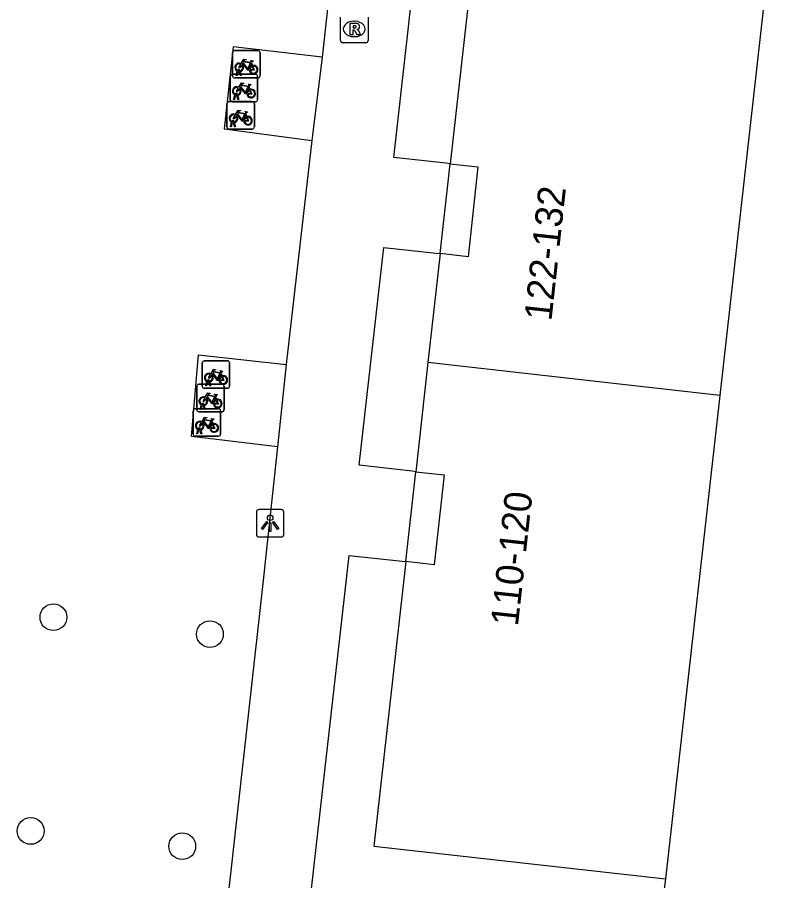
# Model space of a CAD drawing. Extents: x 161928 to 163055, y 386475 to 387428.
# Drawn here: x 162252.98 to 162280.57, y 386677.61 to 386709.1 of the extents above; entities that cross this region are included whole.
import ezdxf

# ---------------------------------------------------------------- set-up
doc = ezdxf.new("R2010")
doc.units = 0
for name, color, linetype in [('IMGEO_Boom', 7, 'Continuous'), ('IMGEO_Fietsenrek', 7, 'Continuous'), ('IMGEO_Grasland_overig', 7, 'Continuous'), ('IMGEO_Lichtpunt', 7, 'Continuous'), ('IMGEO_Pand', 7, 'Continuous'), ('IMGEO_Pand_nummerreeks', 7, 'Continuous'), ('IMGEO_Rioolput', 7, 'Continuous'), ('IMGEO_Voetpad_open', 7, 'Continuous')]:
    doc.layers.add(name, color=color, linetype=linetype)

msp = doc.modelspace()

# ---------------------------------------------------------------- linework, layer by layer
at = {"layer": 'IMGEO_Boom'}
for centre in [(162254.296, 386687.22), (162260.002, 386686.602), (162253.466, 386679.427), (162258.994, 386678.87)]:
    msp.add_circle(centre, 0.489, dxfattribs=at)
at = {"layer": 'IMGEO_Fietsenrek'}
for p, q in [((162260.905, 386707.882), (162261.746, 386707.882)), ((162261.746, 386707.882), (162260.905, 386707.882)), ((162260.83, 386706.957), (162260.83, 386707.798)), ((162260.83, 386707.798), (162260.83, 386706.957)), ((162261.83, 386707.807), (162261.83, 386706.966)), ((162261.83, 386706.966), (162261.83, 386707.807)), ((162261.517, 386707.431), (162261.553, 386707.336)), ((162260.741, 386706.091), (162260.741, 386706.932)), ((162260.741, 386706.932), (162260.741, 386706.091)), ((162260.816, 386707.016), (162261.657, 386707.016)), ((162261.657, 386707.016), (162260.816, 386707.016)), ((162260.957, 386706.966), (162260.996, 386707.126)), ((162260.991, 386706.966), (162260.957, 386706.966)), ((162261.026, 386707.114), (162260.991, 386706.966)), ((162261.068, 386707.138), (162261.067, 386707.142)), ((162261.109, 386706.966), (162261.075, 386707.108)), ((162261.099, 386707.149), (162261.1, 386707.142)), ((162261.107, 386707.112), (162261.142, 386706.966)), ((162261.142, 386706.966), (162261.109, 386706.966)), ((162261.741, 386706.941), (162261.741, 386706.1)), ((162261.741, 386706.1), (162261.741, 386706.941)), ((162261.755, 386706.882), (162260.914, 386706.882)), ((162260.914, 386706.882), (162261.755, 386706.882)), ((162260.979, 386706.272), (162260.978, 386706.276)), ((162261.01, 386706.283), (162261.011, 386706.276)), ((162261.428, 386706.565), (162261.464, 386706.47)), ((162260.698, 386706.021), (162261.539, 386706.021)), ((162261.539, 386706.021), (162260.698, 386706.021)), ((162261.666, 386706.016), (162260.825, 386706.016)), ((162260.825, 386706.016), (162261.666, 386706.016)), ((162260.868, 386706.1), (162260.907, 386706.26)), ((162260.902, 386706.1), (162260.868, 386706.1)), ((162260.937, 386706.248), (162260.902, 386706.1)), ((162261.02, 386706.1), (162260.986, 386706.242)), ((162261.018, 386706.246), (162261.053, 386706.1)), ((162261.053, 386706.1), (162261.02, 386706.1)), ((162260.623, 386705.096), (162260.623, 386705.937)), ((162260.623, 386705.937), (162260.623, 386705.096)), ((162261.623, 386705.946), (162261.623, 386705.105)), ((162261.623, 386705.105), (162261.623, 386705.946)), ((162261.31, 386705.57), (162261.346, 386705.475)), ((162261.548, 386705.021), (162260.707, 386705.021)), ((162260.707, 386705.021), (162261.548, 386705.021)), ((162260.75, 386705.105), (162260.789, 386705.265)), ((162260.784, 386705.105), (162260.75, 386705.105)), ((162260.819, 386705.253), (162260.784, 386705.105)), ((162260.861, 386705.277), (162260.86, 386705.281)), ((162260.902, 386705.105), (162260.868, 386705.247)), ((162260.892, 386705.288), (162260.893, 386705.281)), ((162260.9, 386705.251), (162260.935, 386705.105)), ((162260.935, 386705.105), (162260.902, 386705.105)), ((162259.798, 386696.569), (162260.639, 386696.569)), ((162260.639, 386696.569), (162259.798, 386696.569)), ((162259.723, 386695.644), (162259.723, 386696.485)), ((162259.723, 386696.485), (162259.723, 386695.644)), ((162260.723, 386696.494), (162260.723, 386695.653)), ((162260.723, 386695.653), (162260.723, 386696.494)), ((162260.41, 386696.118), (162260.446, 386696.023)), ((162259.522, 386694.787), (162259.522, 386695.628)), ((162259.522, 386695.628), (162259.522, 386694.787)), ((162259.597, 386695.712), (162260.438, 386695.712)), ((162260.438, 386695.712), (162259.597, 386695.712)), ((162260.648, 386695.569), (162259.807, 386695.569)), ((162259.807, 386695.569), (162260.648, 386695.569)), ((162259.85, 386695.653), (162259.889, 386695.813)), ((162259.884, 386695.653), (162259.85, 386695.653)), ((162259.919, 386695.801), (162259.884, 386695.653)), ((162259.961, 386695.825), (162259.96, 386695.829)), ((162260.002, 386695.653), (162259.968, 386695.795)), ((162259.992, 386695.836), (162259.993, 386695.829)), ((162260, 386695.799), (162260.035, 386695.653)), ((162260.035, 386695.653), (162260.002, 386695.653)), ((162260.522, 386695.637), (162260.522, 386694.796)), ((162260.522, 386694.796), (162260.522, 386695.637)), ((162260.209, 386695.261), (162260.245, 386695.166)), ((162259.649, 386694.796), (162259.688, 386694.956)), ((162259.718, 386694.944), (162259.683, 386694.796)), ((162259.76, 386694.968), (162259.759, 386694.972)), ((162259.801, 386694.796), (162259.767, 386694.938)), ((162259.791, 386694.979), (162259.792, 386694.972)), ((162259.799, 386694.942), (162259.834, 386694.796)), ((162259.393, 386693.895), (162259.393, 386694.736)), ((162259.393, 386694.736), (162259.393, 386693.895)), ((162259.468, 386694.82), (162260.309, 386694.82)), ((162260.309, 386694.82), (162259.468, 386694.82)), ((162260.447, 386694.712), (162259.606, 386694.712)), ((162259.606, 386694.712), (162260.447, 386694.712)), ((162259.683, 386694.796), (162259.649, 386694.796)), ((162259.834, 386694.796), (162259.801, 386694.796)), ((162260.393, 386694.745), (162260.393, 386693.904)), ((162260.393, 386693.904), (162260.393, 386694.745)), ((162260.08, 386694.369), (162260.116, 386694.274)), ((162259.52, 386693.904), (162259.559, 386694.064)), ((162259.589, 386694.052), (162259.554, 386693.904)), ((162259.631, 386694.076), (162259.63, 386694.08)), ((162259.672, 386693.904), (162259.638, 386694.046)), ((162259.662, 386694.087), (162259.663, 386694.08)), ((162259.67, 386694.05), (162259.705, 386693.904)), ((162260.318, 386693.82), (162259.477, 386693.82)), ((162259.477, 386693.82), (162260.318, 386693.82)), ((162259.554, 386693.904), (162259.52, 386693.904)), ((162259.705, 386693.904), (162259.672, 386693.904))]:
    msp.add_line(p, q, dxfattribs=at)
for points in [[(162261.143, 386707.408), (162261.238, 386707.572), (162261.324, 386707.558), (162261.326, 386707.549), (162261.27, 386707.538), (162261.243, 386707.493), (162261.499, 386707.452)], [(162261.164, 386707.356), (162261.112, 386707.266), (162261.072, 386707.241), (162261.073, 386707.288), (162261.128, 386707.382)], [(162261.439, 386707.164), (162261.389, 386707.164), (162261.198, 386707.415), (162261.179, 386707.383)], [(162261.486, 386707.427), (162261.229, 386707.468), (162261.212, 386707.439), (162261.379, 386707.219), (162261.486, 386707.427)], [(162261.534, 386707.329), (162261.504, 386707.406), (162261.395, 386707.188), (162261.438, 386707.188)], [(162261.468, 386707.188), (162261.588, 386707.187), (162261.544, 386707.301)], [(162261.564, 386707.308), (162261.619, 386707.163), (162261.469, 386707.163)], [(162261.499, 386707.452), (162261.524, 386707.501), (162261.518, 386707.505), (162261.495, 386707.509), (162261.483, 386707.516), (162261.482, 386707.519), (162261.484, 386707.524), (162261.579, 386707.509), (162261.581, 386707.499), (162261.571, 386707.486), (162261.559, 386707.48), (162261.545, 386707.486), (162261.517, 386707.431)], [(162261.054, 386706.542), (162261.149, 386706.706), (162261.235, 386706.692), (162261.237, 386706.683), (162261.181, 386706.672), (162261.154, 386706.627), (162261.41, 386706.586)], [(162261.397, 386706.561), (162261.14, 386706.602), (162261.123, 386706.573), (162261.29, 386706.353), (162261.397, 386706.561)], [(162261.41, 386706.586), (162261.435, 386706.635), (162261.429, 386706.639), (162261.406, 386706.643), (162261.394, 386706.65), (162261.393, 386706.653), (162261.395, 386706.658), (162261.49, 386706.643), (162261.492, 386706.633), (162261.482, 386706.62), (162261.47, 386706.614), (162261.456, 386706.62), (162261.428, 386706.565)], [(162261.075, 386706.49), (162261.023, 386706.4), (162260.983, 386706.375), (162260.984, 386706.422), (162261.039, 386706.516)], [(162261.35, 386706.298), (162261.3, 386706.298), (162261.109, 386706.549), (162261.09, 386706.517)], [(162261.445, 386706.463), (162261.415, 386706.54), (162261.306, 386706.322), (162261.349, 386706.322)], [(162261.379, 386706.322), (162261.499, 386706.321), (162261.455, 386706.435)], [(162261.475, 386706.442), (162261.53, 386706.297), (162261.38, 386706.297)], [(162260.936, 386705.547), (162261.031, 386705.711), (162261.117, 386705.697), (162261.119, 386705.688), (162261.063, 386705.677), (162261.036, 386705.632), (162261.292, 386705.591)], [(162261.292, 386705.591), (162261.317, 386705.64), (162261.311, 386705.644), (162261.288, 386705.648), (162261.276, 386705.655), (162261.275, 386705.658), (162261.277, 386705.663), (162261.372, 386705.648), (162261.374, 386705.638), (162261.364, 386705.625), (162261.352, 386705.619), (162261.338, 386705.625), (162261.31, 386705.57)], [(162260.957, 386705.495), (162260.905, 386705.405), (162260.865, 386705.38), (162260.866, 386705.427), (162260.921, 386705.521)], [(162261.232, 386705.303), (162261.182, 386705.303), (162260.991, 386705.554), (162260.972, 386705.522)], [(162261.279, 386705.566), (162261.022, 386705.607), (162261.005, 386705.578), (162261.172, 386705.358), (162261.279, 386705.566)], [(162261.327, 386705.468), (162261.297, 386705.545), (162261.188, 386705.327), (162261.231, 386705.327)], [(162261.261, 386705.327), (162261.381, 386705.326), (162261.337, 386705.44)], [(162261.357, 386705.447), (162261.412, 386705.302), (162261.262, 386705.302)], [(162260.036, 386696.095), (162260.131, 386696.259), (162260.217, 386696.245), (162260.219, 386696.236), (162260.163, 386696.225), (162260.136, 386696.18), (162260.392, 386696.139)], [(162260.392, 386696.139), (162260.417, 386696.188), (162260.411, 386696.192), (162260.388, 386696.196), (162260.376, 386696.203), (162260.375, 386696.206), (162260.377, 386696.211), (162260.472, 386696.196), (162260.474, 386696.186), (162260.464, 386696.173), (162260.452, 386696.167), (162260.438, 386696.173), (162260.41, 386696.118)], [(162260.057, 386696.043), (162260.005, 386695.953), (162259.965, 386695.928), (162259.966, 386695.975), (162260.021, 386696.069)], [(162260.332, 386695.851), (162260.282, 386695.851), (162260.091, 386696.102), (162260.072, 386696.07)], [(162260.379, 386696.114), (162260.122, 386696.155), (162260.105, 386696.126), (162260.272, 386695.906), (162260.379, 386696.114)], [(162260.427, 386696.016), (162260.397, 386696.093), (162260.288, 386695.875), (162260.331, 386695.875)], [(162260.361, 386695.875), (162260.481, 386695.874), (162260.437, 386695.988)], [(162260.457, 386695.995), (162260.512, 386695.85), (162260.362, 386695.85)], [(162259.835, 386695.238), (162259.93, 386695.402), (162260.016, 386695.388), (162260.018, 386695.379), (162259.962, 386695.368), (162259.935, 386695.323), (162260.191, 386695.282)], [(162260.178, 386695.257), (162259.921, 386695.298), (162259.904, 386695.269), (162260.071, 386695.049), (162260.178, 386695.257)], [(162260.191, 386695.282), (162260.216, 386695.331), (162260.21, 386695.335), (162260.187, 386695.339), (162260.175, 386695.346), (162260.174, 386695.349), (162260.176, 386695.354), (162260.271, 386695.339), (162260.273, 386695.329), (162260.263, 386695.316), (162260.251, 386695.31), (162260.237, 386695.316), (162260.209, 386695.261)], [(162259.856, 386695.186), (162259.804, 386695.096), (162259.764, 386695.071), (162259.765, 386695.118), (162259.82, 386695.212)], [(162260.131, 386694.994), (162260.081, 386694.994), (162259.89, 386695.245), (162259.871, 386695.213)], [(162260.226, 386695.159), (162260.196, 386695.236), (162260.087, 386695.018), (162260.13, 386695.018)], [(162260.16, 386695.018), (162260.28, 386695.017), (162260.236, 386695.131)], [(162260.256, 386695.138), (162260.311, 386694.993), (162260.161, 386694.993)], [(162259.727, 386694.294), (162259.675, 386694.204), (162259.635, 386694.179), (162259.636, 386694.226), (162259.691, 386694.32)], [(162259.706, 386694.346), (162259.801, 386694.51), (162259.887, 386694.496), (162259.889, 386694.487), (162259.833, 386694.476), (162259.806, 386694.431), (162260.062, 386694.39)], [(162260.002, 386694.102), (162259.952, 386694.102), (162259.761, 386694.353), (162259.742, 386694.321)], [(162260.049, 386694.365), (162259.792, 386694.406), (162259.775, 386694.377), (162259.942, 386694.157), (162260.049, 386694.365)], [(162260.097, 386694.267), (162260.067, 386694.344), (162259.958, 386694.126), (162260.001, 386694.126)], [(162260.062, 386694.39), (162260.087, 386694.439), (162260.081, 386694.443), (162260.058, 386694.447), (162260.046, 386694.454), (162260.045, 386694.457), (162260.047, 386694.462), (162260.142, 386694.447), (162260.144, 386694.437), (162260.134, 386694.424), (162260.122, 386694.418), (162260.108, 386694.424), (162260.08, 386694.369)], [(162260.031, 386694.126), (162260.151, 386694.125), (162260.107, 386694.239)], [(162260.127, 386694.246), (162260.182, 386694.101), (162260.032, 386694.101)]]:
    msp.add_lwpolyline(points, dxfattribs=at)
for centre, radius, start, end in [((162260.908, 386707.804), 0.0779, 92.4484, 184.2845), ((162260.908, 386707.804), 0.0779, 92.4484, 184.2845), ((162261.752, 386707.804), 0.0779, 2.4484, 94.2845), ((162261.752, 386707.804), 0.0779, 2.4484, 94.2845), ((162261.07, 386707.267), 0.159, 62.6766, 242.1369), ((162261.07, 386707.267), 0.129, 63.3192, 238.903), ((162261.07, 386707.267), 0.129, 283.6043, 43.4302), ((162261.07, 386707.267), 0.159, 283.5766, 46.6042), ((162261.597, 386707.183), 0.159, 113.3408, 178.3217), ((162261.597, 386707.183), 0.159, 187.0065, 105.7708), ((162261.597, 386707.183), 0.129, 113.923, 177.9556), ((162261.597, 386707.183), 0.129, 188.6715, 104.5883), ((162260.819, 386706.938), 0.0779, 92.4484, 184.2845), ((162260.819, 386706.938), 0.0779, 92.4484, 184.2845), ((162260.908, 386706.96), 0.0779, 182.4484, 274.2845), ((162260.908, 386706.96), 0.0779, 182.4484, 274.2845), ((162261.05, 386707.138), 0.0499, 12.8025, 158.6934), ((162261.07, 386707.267), 0.159, 253.9967, 271.7867), ((162261.05, 386707.138), 0.0174, 12.8025, 163.4502), ((162261.07, 386707.267), 0.129, 253.415, 269.0204), ((162261.663, 386706.938), 0.0779, 2.4484, 94.2845), ((162261.663, 386706.938), 0.0779, 2.4484, 94.2845), ((162261.752, 386706.96), 0.0779, 272.4484, 4.2845), ((162261.752, 386706.96), 0.0779, 272.4484, 4.2845), ((162260.981, 386706.401), 0.159, 62.6766, 242.1369), ((162260.981, 386706.401), 0.129, 63.3192, 238.903), ((162260.961, 386706.272), 0.0499, 12.8025, 158.6934), ((162260.961, 386706.272), 0.0174, 12.8025, 163.4502), ((162260.981, 386706.401), 0.129, 253.415, 269.0204), ((162260.981, 386706.401), 0.129, 283.6043, 43.4302), ((162260.981, 386706.401), 0.159, 283.5766, 46.6042), ((162261.508, 386706.317), 0.159, 113.3408, 178.3217), ((162261.508, 386706.317), 0.159, 187.0065, 105.7708), ((162261.508, 386706.317), 0.129, 113.923, 177.9556), ((162261.508, 386706.317), 0.129, 188.6715, 104.5883), ((162260.701, 386705.943), 0.0779, 92.4484, 184.2845), ((162260.701, 386705.943), 0.0779, 92.4484, 184.2845), ((162260.819, 386706.094), 0.0779, 182.4484, 274.2845), ((162260.819, 386706.094), 0.0779, 182.4484, 274.2845), ((162260.981, 386706.401), 0.159, 253.9967, 271.7867), ((162261.545, 386705.943), 0.0779, 2.4484, 94.2845), ((162261.545, 386705.943), 0.0779, 2.4484, 94.2845), ((162261.663, 386706.094), 0.0779, 272.4484, 4.2845), ((162261.663, 386706.094), 0.0779, 272.4484, 4.2845), ((162260.863, 386705.406), 0.159, 62.6766, 242.1369), ((162260.863, 386705.406), 0.129, 63.3192, 238.903), ((162260.863, 386705.406), 0.129, 283.6043, 43.4302), ((162260.863, 386705.406), 0.159, 283.5766, 46.6042), ((162261.39, 386705.322), 0.159, 113.3408, 178.3217), ((162261.39, 386705.322), 0.159, 187.0065, 105.7708), ((162261.39, 386705.322), 0.129, 113.923, 177.9556), ((162261.39, 386705.322), 0.129, 188.6715, 104.5883), ((162260.701, 386705.099), 0.0779, 182.4484, 274.2845), ((162260.701, 386705.099), 0.0779, 182.4484, 274.2845), ((162260.843, 386705.277), 0.0499, 12.8025, 158.6934), ((162260.863, 386705.406), 0.159, 253.9967, 271.7867), ((162260.843, 386705.277), 0.0174, 12.8025, 163.4502), ((162260.863, 386705.406), 0.129, 253.415, 269.0204), ((162261.545, 386705.099), 0.0779, 272.4484, 4.2845), ((162261.545, 386705.099), 0.0779, 272.4484, 4.2845), ((162259.801, 386696.491), 0.0779, 92.4484, 184.2845), ((162259.801, 386696.491), 0.0779, 92.4484, 184.2845), ((162260.645, 386696.491), 0.0779, 2.4484, 94.2845), ((162260.645, 386696.491), 0.0779, 2.4484, 94.2845), ((162259.963, 386695.954), 0.159, 62.6766, 242.1369), ((162259.963, 386695.954), 0.129, 63.3192, 238.903), ((162259.963, 386695.954), 0.129, 283.6043, 43.4302), ((162259.963, 386695.954), 0.159, 283.5766, 46.6042), ((162260.49, 386695.87), 0.159, 113.3408, 178.3217), ((162260.49, 386695.87), 0.159, 187.0065, 105.7708), ((162260.49, 386695.87), 0.129, 113.923, 177.9556), ((162260.49, 386695.87), 0.129, 188.6715, 104.5883), ((162259.6, 386695.634), 0.0779, 92.4484, 184.2845), ((162259.6, 386695.634), 0.0779, 92.4484, 184.2845), ((162259.801, 386695.647), 0.0779, 182.4484, 274.2845), ((162259.801, 386695.647), 0.0779, 182.4484, 274.2845), ((162259.943, 386695.825), 0.0499, 12.8025, 158.6934), ((162259.963, 386695.954), 0.159, 253.9967, 271.7867), ((162259.943, 386695.825), 0.0174, 12.8025, 163.4502), ((162259.963, 386695.954), 0.129, 253.415, 269.0204), ((162260.444, 386695.634), 0.0779, 2.4484, 94.2845), ((162260.444, 386695.634), 0.0779, 2.4484, 94.2845), ((162260.645, 386695.647), 0.0779, 272.4484, 4.2845), ((162260.645, 386695.647), 0.0779, 272.4484, 4.2845), ((162259.762, 386695.097), 0.159, 62.6766, 242.1369), ((162259.762, 386695.097), 0.129, 63.3192, 238.903), ((162259.742, 386694.968), 0.0499, 12.8025, 158.6934), ((162259.762, 386695.097), 0.159, 253.9967, 271.7867), ((162259.742, 386694.968), 0.0174, 12.8025, 163.4502), ((162259.762, 386695.097), 0.129, 253.415, 269.0204), ((162259.762, 386695.097), 0.129, 283.6043, 43.4302), ((162259.762, 386695.097), 0.159, 283.5766, 46.6042), ((162260.289, 386695.013), 0.159, 113.3408, 178.3217), ((162260.289, 386695.013), 0.159, 187.0065, 105.7708), ((162260.289, 386695.013), 0.129, 113.923, 177.9556), ((162260.289, 386695.013), 0.129, 188.6715, 104.5883), ((162259.471, 386694.742), 0.0779, 92.4484, 184.2845), ((162259.471, 386694.742), 0.0779, 92.4484, 184.2845), ((162259.6, 386694.79), 0.0779, 182.4484, 274.2845), ((162259.6, 386694.79), 0.0779, 182.4484, 274.2845), ((162260.315, 386694.742), 0.0779, 2.4484, 94.2845), ((162260.315, 386694.742), 0.0779, 2.4484, 94.2845), ((162260.444, 386694.79), 0.0779, 272.4484, 4.2845), ((162260.444, 386694.79), 0.0779, 272.4484, 4.2845), ((162259.633, 386694.205), 0.159, 62.6766, 242.1369), ((162259.633, 386694.205), 0.129, 63.3192, 238.903), ((162259.633, 386694.205), 0.159, 283.5766, 46.6042), ((162259.613, 386694.076), 0.0499, 12.8025, 158.6934), ((162259.633, 386694.205), 0.159, 253.9967, 271.7867), ((162259.613, 386694.076), 0.0174, 12.8025, 163.4502), ((162259.633, 386694.205), 0.129, 253.415, 269.0204), ((162259.633, 386694.205), 0.129, 283.6043, 43.4302), ((162260.16, 386694.121), 0.159, 113.3408, 178.3217), ((162260.16, 386694.121), 0.159, 187.0065, 105.7708), ((162260.16, 386694.121), 0.129, 113.923, 177.9556), ((162260.16, 386694.121), 0.129, 188.6715, 104.5883), ((162259.471, 386693.898), 0.0779, 182.4484, 274.2845), ((162259.471, 386693.898), 0.0779, 182.4484, 274.2845), ((162260.315, 386693.898), 0.0779, 272.4484, 4.2845), ((162260.315, 386693.898), 0.0779, 272.4484, 4.2845)]:
    msp.add_arc(centre, radius, start, end, dxfattribs=at)
at = {"layer": 'IMGEO_Grasland_overig'}
msp.add_lwpolyline([(162276.622, 386677.674), (162276.413, 386676.138), (162263.71, 386677.32)], dxfattribs=at)
at = {"layer": 'IMGEO_Lichtpunt'}
for p, q in [((162261.701, 386691.048), (162261.701, 386690.241)), ((162261.701, 386691.048), (162261.701, 386690.241)), ((162262.603, 386691.143), (162261.795, 386691.143)), ((162262.603, 386691.143), (162261.795, 386691.143)), ((162262.697, 386690.241), (162262.697, 386691.048)), ((162262.697, 386690.241), (162262.697, 386691.048)), ((162261.795, 386690.147), (162262.603, 386690.147)), ((162261.795, 386690.147), (162262.603, 386690.147))]:
    msp.add_line(p, q, dxfattribs=at)
for points in [[(162262.075, 386690.712), (162262.114, 386690.684), (162261.926, 386690.422), (162261.888, 386690.449), (162262.075, 386690.712)], [(162262.177, 386690.664), (162262.224, 386690.664), (162262.224, 386690.342), (162262.177, 386690.342), (162262.177, 386690.664)], [(162262.287, 386690.684), (162262.325, 386690.711), (162262.512, 386690.449), (162262.473, 386690.421), (162262.287, 386690.684)]]:
    msp.add_lwpolyline(points, dxfattribs=at)
msp.add_circle((162262.2, 386690.846), 0.0994, dxfattribs=at)
for centre, start, end in [((162261.795, 386691.048), 90, 180), ((162261.795, 386691.048), 90, 180), ((162262.603, 386691.048), 0, 90), ((162262.603, 386691.048), 0, 90), ((162261.795, 386690.241), 180, 270), ((162261.795, 386690.241), 180, 270), ((162262.603, 386690.241), 270, 0), ((162262.603, 386690.241), 270, 360)]:
    msp.add_arc(centre, 0.0946, start, end, dxfattribs=at)
at = {"layer": 'IMGEO_Pand'}
for points in [[(162269.917, 386714.021), (162268.767, 386703.756)], [(162280.566, 386712.844), (162278.599, 386695.307)], [(162268.767, 386703.756), (162269.775, 386703.646), (162269.416, 386700.365), (162268.4, 386700.476)], [(162268.4, 386700.476), (162267.955, 386696.501)], [(162267.955, 386696.501), (162267.51, 386692.526)], [(162278.599, 386695.307), (162267.955, 386696.501)], [(162278.599, 386695.307), (162276.622, 386677.674)], [(162267.51, 386692.526), (162268.544, 386692.413), (162268.184, 386689.133), (162267.143, 386689.247)], [(162267.143, 386689.247), (162265.981, 386678.865), (162276.622, 386677.674)]]:
    msp.add_lwpolyline(points, dxfattribs=at)
at = {"layer": 'IMGEO_Rioolput'}
for p, q in [((162264.768, 386708.243), (162264.768, 386709.095)), ((162265.256, 386708.949), (162265.281, 386708.949)), ((162265.769, 386709.095), (162265.769, 386708.243)), ((162265.695, 386708.169), (162264.843, 386708.169)), ((162265.279, 386708.389), (162265.254, 386708.389))]:
    msp.add_line(p, q, dxfattribs=at)
for points in [[(162264.768, 386708.243), (162264.768, 386709.095)], [(162265.357, 386708.867), (162265.105, 386708.869), (162265.105, 386708.469)], [(162265.769, 386709.095), (162265.769, 386708.243)], [(162265.105, 386708.469), (162265.229, 386708.469), (162265.229, 386708.631), (162265.24, 386708.631)], [(162265.283, 386708.788), (162265.229, 386708.788), (162265.229, 386708.707)], [(162265.229, 386708.707), (162265.281, 386708.707)], [(162265.287, 386708.602), (162265.358, 386708.469), (162265.498, 386708.469), (162265.433, 386708.595)], [(162265.695, 386708.169), (162264.843, 386708.169)]]:
    msp.add_lwpolyline(points, dxfattribs=at)
for centre, radius, start, end in [((162265.356, 386708.757), 0.109, 350.3612, 89.416), ((162265.239, 386708.578), 0.0533, 26.0293, 88.6989), ((162265.265, 386708.896), 0.19, 274.7715, 282.9687), ((162265.289, 386708.692), 0.0964, 77.0061, 93.1865), ((162265.303, 386708.749), 0.0378, 276.6634, 79.6772), ((162265.354, 386708.757), 0.112, 277.5842, 350.9817), ((162265.338, 386708.542), 0.108, 29.5134, 73.7905), ((162264.845, 386708.245), 0.0765, 181.552, 268.448), ((162264.845, 386708.245), 0.0765, 181.552, 268.448), ((162265.693, 386708.245), 0.0765, 271.552, 358.448), ((162265.693, 386708.245), 0.0765, 271.552, 358.448)]:
    msp.add_arc(centre, radius, start, end, dxfattribs=at)
for centre, major_axis, ratio, start_param, end_param in [((162265.255, 386708.669), (-0.387, 0.002), 0.722429, 4.712389, 7.853982), ((162265.28, 386708.669), (-0.39, 0.002), 0.717154, 1.570796, 4.712389)]:
    msp.add_ellipse(centre, major_axis=major_axis, ratio=ratio, start_param=start_param, end_param=end_param, dxfattribs=at)
at = {"layer": 'IMGEO_Voetpad_open'}
for points in [[(162265.689, 386722.086), (162264.105, 386707.754), (162264.091, 386707.639)], [(162268.767, 386703.756), (162268.611, 386703.773), (162266.71, 386703.981), (162268.309, 386718.183), (162270.169, 386717.978), (162270.358, 386717.957)], [(162264.091, 386707.639), (162260.853, 386708.016), (162260.528, 386705.028), (162263.719, 386704.596)], [(162264.091, 386707.639), (162263.741, 386704.792), (162263.719, 386704.596)], [(162263.719, 386704.596), (162262.8, 386696.541), (162262.789, 386696.438)], [(162268.4, 386700.476), (162268.767, 386703.756)], [(162267.51, 386692.526), (162267.38, 386692.54), (162265.448, 386692.762), (162266.341, 386700.702), (162268.251, 386700.492), (162268.4, 386700.476)], [(162262.467, 386693.434), (162259.33, 386693.811), (162259.59, 386696.782), (162262.789, 386696.438)], [(162262.789, 386696.438), (162262.467, 386693.434)], [(162262.467, 386693.434), (162261.932, 386688.446), (162260.486, 386675.473)], [(162267.143, 386689.247), (162267.51, 386692.526)], [(162263.71, 386677.32), (162265.077, 386689.473), (162267.02, 386689.26), (162267.143, 386689.247)]]:
    msp.add_lwpolyline(points, dxfattribs=at)

# ---------------------------------------------------------------- texts
at = {"layer": 'IMGEO_Pand_nummerreeks'}
for s, rotation, p in [('122-132', 83.7557, (162272.457, 386697.998)), ('110-120', 83.7365, (162271.235, 386686.864))]:
    msp.add_text(s, height=1, rotation=rotation, dxfattribs=at).set_placement(p)

doc.saveas('drawing.dxf')
